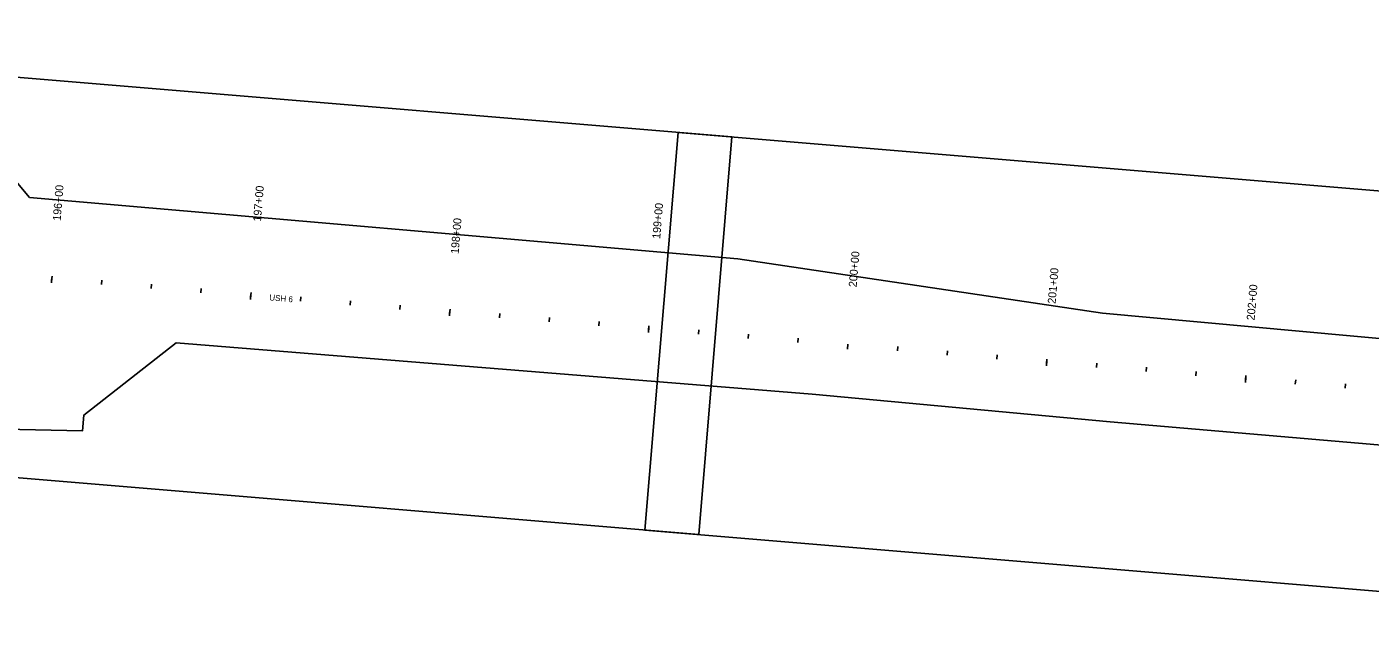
# Model space of a CAD drawing. Extents: x 20499876 to 20505320, y 7953544 to 7954108.
# Drawn here: x 20503290 to 20503963, y 7953584 to 7953888 of the extents above; entities that cross this region are included whole.
import ezdxf

# ---------------------------------------------------------------- set-up
doc = ezdxf.new("R2010")
doc.units = 0
for name, color, linetype in [('Draft_0', 7, 'Continuous'), ('Draft_7', 7, 'Continuous'), ('Drainage- Pipe', 7, 'Continuous'), ('PS_CONST', 7, 'Continuous'), ('Wall', 7, 'Continuous')]:
    doc.layers.add(name, color=color, linetype=linetype)

msp = doc.modelspace()

# ---------------------------------------------------------------- linework, layer by layer
at = {"layer": 'Draft_7'}
for p, q in [((20503302.9, 7953762.68), (20503302.7, 7953760.24)), ((20503327.71, 7953759.38), (20503327.89, 7953761.55)), ((20503352.63, 7953757.3), (20503352.81, 7953759.47)), ((20503377.54, 7953755.22), (20503377.72, 7953757.39)), ((20503402.55, 7953754.36), (20503402.35, 7953751.92)), ((20503427.37, 7953751.06), (20503427.55, 7953753.24)), ((20503452.28, 7953748.98), (20503452.46, 7953751.16)), ((20503477.19, 7953746.9), (20503477.37, 7953749.08)), ((20503502.21, 7953746.04), (20503502, 7953743.6)), ((20503527.02, 7953742.74), (20503527.2, 7953744.92)), ((20503551.93, 7953740.66), (20503552.11, 7953742.84)), ((20503576.85, 7953738.59), (20503577.03, 7953740.76)), ((20503601.86, 7953737.73), (20503601.66, 7953735.29)), ((20503626.67, 7953734.43), (20503626.85, 7953736.6)), ((20503651.59, 7953732.35), (20503651.77, 7953734.52)), ((20503676.5, 7953730.27), (20503676.68, 7953732.45)), ((20503701.51, 7953729.41), (20503701.31, 7953726.97)), ((20503726.33, 7953726.11), (20503726.51, 7953728.29)), ((20503751.24, 7953724.03), (20503751.42, 7953726.21)), ((20503776.15, 7953721.95), (20503776.33, 7953724.13)), ((20503801.17, 7953721.09), (20503800.96, 7953718.65)), ((20503825.98, 7953717.79), (20503826.16, 7953719.97)), ((20503850.89, 7953715.72), (20503851.08, 7953717.89)), ((20503875.81, 7953713.64), (20503875.99, 7953715.81)), ((20503900.82, 7953712.78), (20503900.62, 7953710.34)), ((20503925.63, 7953709.48), (20503925.82, 7953711.65)), ((20503950.55, 7953707.4), (20503950.73, 7953709.58))]:
    msp.add_line(p, q, dxfattribs=at)
at = {"layer": 'Drainage- Pipe'}
for points in [[(20503018.63, 7953885.52), (20503002, 7953686.21), (20503626.83, 7953634.07), (20503643.46, 7953833.37)], [(20503616.55, 7953835.62), (20503599.92, 7953636.31), (20504224.75, 7953584.17), (20504241.38, 7953783.48)]]:
    msp.add_lwpolyline(points, close=True, dxfattribs=at)
at = {"layer": 'PS_CONST'}
for p, q in [((20503302.8, 7953761.46), (20503302.98, 7953763.63)), ((20503402.45, 7953753.14), (20503402.63, 7953755.32)), ((20503502.11, 7953744.82), (20503502.29, 7953747)), ((20503601.76, 7953736.51), (20503601.94, 7953738.68)), ((20503701.51, 7953729.41), (20503701.31, 7953726.97)), ((20503801.07, 7953719.87), (20503801.25, 7953722.05)), ((20503900.72, 7953711.56), (20503900.9, 7953713.73))]:
    msp.add_line(p, q, dxfattribs=at)
at = {"layer": 'Wall'}
for points in [[(20502579.49, 7953887.98), (20502593.01, 7953888.5), (20502597.99, 7953888.06), (20502663.24, 7953867.31), (20502743.17, 7953845.01), (20502960.26, 7953827.03), (20503149.04, 7953802.5), (20503172.51, 7953801.74), (20503181.34, 7953817.32), (20503201.28, 7953847.18), (20503257.87, 7953843.36), (20503291.71, 7953802.91), (20503646.48, 7953772.26), (20503829.09, 7953744.97), (20504079.02, 7953722.08)], [(20503994.1, 7953676.75), (20503832.88, 7953690.55), (20503683.62, 7953704.36), (20503365.12, 7953730.13), (20503318.98, 7953693.96), (20503318.32, 7953686.11), (20503255.28, 7953687.43), (20503201.41, 7953693.27), (20503166.1, 7953705.05), (20503168.96, 7953719.94), (20503119.74, 7953739.09), (20502805.68, 7953763.59), (20502567.99, 7953764)]]:
    msp.add_lwpolyline(points, dxfattribs=at)

# ---------------------------------------------------------------- texts
at = {"layer": 'Draft_0'}
msp.add_text('USH 6', height=3, rotation=355, dxfattribs=at).set_placement((20503411.7, 7953751.46))
at = {"layer": 'Draft_7'}
for s, p in [('196+00', (20503307.29, 7953791.18)), ('197+00', (20503407.62, 7953790.76)), ('199+00', (20503607.55, 7953782.1)), ('198+00', (20503506.6, 7953774.55)), ('200+00', (20503705.91, 7953757.92)), ('201+00', (20503805.56, 7953749.6)), ('202+00', (20503905.21, 7953741.29))]:
    msp.add_text(s, height=4.008, rotation=85.22957, dxfattribs=at).set_placement(p)
at = {"layer": 'PS_CONST'}
msp.add_text('200+00', height=4.008, rotation=85.22957, dxfattribs=at).set_placement((20503705.91, 7953757.92))

doc.saveas('drawing.dxf')
